Omron CX-Programmer project NuevoProyecto (CX-Programmer 9.50)

# PLC NewPLC1: CP1L-E EM

## Global symbols (name address type ; comment)
D0 CHANNEL  ; 0
T0002 BOOL  ; T2
T0003 BOOL  ; T3
T0004 BOOL  ; T4
T0005 BOOL  ; T5
T0006 BOOL  ; T6
T0007 BOOL  ; T7
T0008 BOOL  ; T8

## Program P10_2 (cyclic task 0)
Local symbols
EV1 100.04 BOOL  ; EV1=X6·Pm'
EV2 100.05 BOOL  ; EV2=X13·Pm'
EVA 100.00 BOOL  ; EVA=(X1+X10)·Pm'
EVB 100.01 BOOL  ; EVB=(X2+X9)Pm'
EVC 100.02 BOOL  ; EVC=X3·Pm'
EVD 100.03 BOOL  ; EVD=X8·Pm'
Etapa_0 10.00 BOOL
Etapa_1 10.01 BOOL
Etapa_10 10.10 BOOL
Etapa_11 10.11 BOOL
Etapa_12 10.12 BOOL
Etapa_13 10.13 BOOL
Etapa_14 10.14 BOOL
Etapa_2 10.02 BOOL
Etapa_3 10.03 BOOL
Etapa_4 10.04 BOOL
Etapa_5 10.05 BOOL
Etapa_6 10.06 BOOL
Etapa_7 10.07 BOOL
Etapa_8 10.08 BOOL
Etapa_9 10.09 BOOL
FC1 0.04 BOOL  ; Final carrera 1 (CNA)
FC2 0.05 BOOL  ; Final carrera 2 (CNA)
FC3 0.06 BOOL  ; Final carrera 3 (CNA)
FC4 0.07 BOOL  ; Final carrera 4 (CNA)
KCD 100.06 BOOL  ; KCD=(X1+X2+X3+X4)·Pm'
KCI 100.07 BOOL  ; KCI=(X8+X9+X10+X11)·Pm'
KV1D 101.00 BOOL  ; KV1D=X5·Pm'
KV1I 101.01 BOOL  ; KV1I=X7·Pm'
KV2D 101.02 BOOL  ; KV2D=X14·Pm'
KV2I 101.03 BOOL  ; KV2I=X12·Pm'
P 0.02 BOOL  ; Pulsador de paro (CNC)
Pm 15.00 BOOL  ; Pm=P·X0'+Pm·R'
R 0.03 BOOL  ; Pulsador de rearme (CNA)
m1 0.00 BOOL  ; Pulsador de marcha mezcla 1 (CNA)
m2 0.01 BOOL  ; Pulsador de marcha mezcla 2 (CNA)

### Section Sección1_Etapa_0

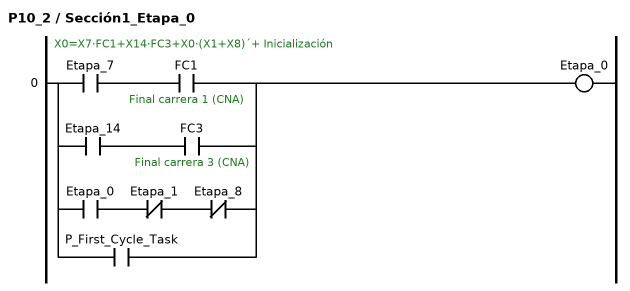
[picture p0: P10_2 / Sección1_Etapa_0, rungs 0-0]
; rung 0: X0=X7·FC1+X14·FC3+X0·(X1+X8)´+ Inicialización
LD Etapa_7
AND FC1  ; Final carrera 1 (CNA)
LD Etapa_14
AND FC3  ; Final carrera 3 (CNA)
ORLD
LD Etapa_0
ANDNOT Etapa_1
ANDNOT Etapa_8
ORLD
OR P_First_Cycle_Task
OUT Etapa_0

### Section Sección2_Mezcla_1_Etapas_1_a_7

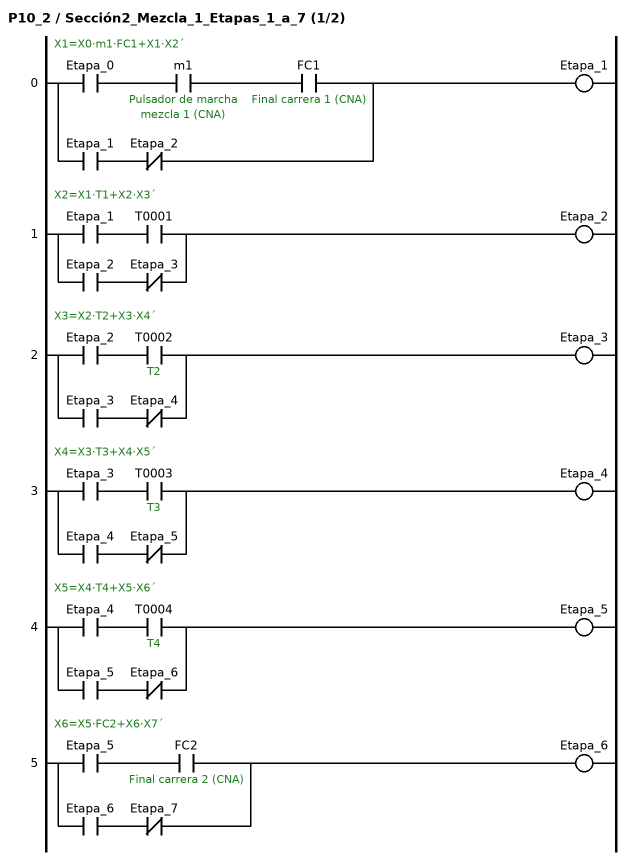
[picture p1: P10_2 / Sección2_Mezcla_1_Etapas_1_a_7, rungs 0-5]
; rung 0: X1=X0·m1·FC1+X1·X2´
LD Etapa_0
AND m1  ; Pulsador de marcha mezcla 1 (CNA)
AND FC1  ; Final carrera 1 (CNA)
LD Etapa_1
ANDNOT Etapa_2
ORLD
OUT Etapa_1
; rung 1: X2=X1·T1+X2·X3´
LD Etapa_1
AND T0001
LD Etapa_2
ANDNOT Etapa_3
ORLD
OUT Etapa_2
; rung 2: X3=X2·T2+X3·X4´
LD Etapa_2
AND T0002  ; T2
LD Etapa_3
ANDNOT Etapa_4
ORLD
OUT Etapa_3
; rung 3: X4=X3·T3+X4·X5´
LD Etapa_3
AND T0003  ; T3
LD Etapa_4
ANDNOT Etapa_5
ORLD
OUT Etapa_4
; rung 4: X5=X4·T4+X5·X6´
LD Etapa_4
AND T0004  ; T4
LD Etapa_5
ANDNOT Etapa_6
ORLD
OUT Etapa_5
; rung 5: X6=X5·FC2+X6·X7´
LD Etapa_5
AND FC2  ; Final carrera 2 (CNA)
LD Etapa_6
ANDNOT Etapa_7
ORLD
OUT Etapa_6

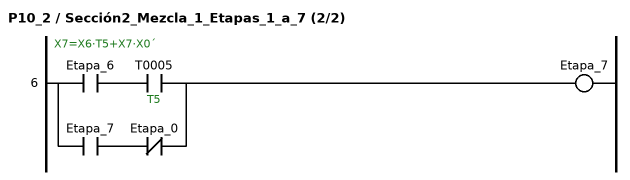
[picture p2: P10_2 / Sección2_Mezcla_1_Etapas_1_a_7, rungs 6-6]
; rung 6: X7=X6·T5+X7·X0´
LD Etapa_6
AND T0005  ; T5
LD Etapa_7
ANDNOT Etapa_0
ORLD
OUT Etapa_7

### Section Sección3_Mezcla_2_Etapas_8_a_14

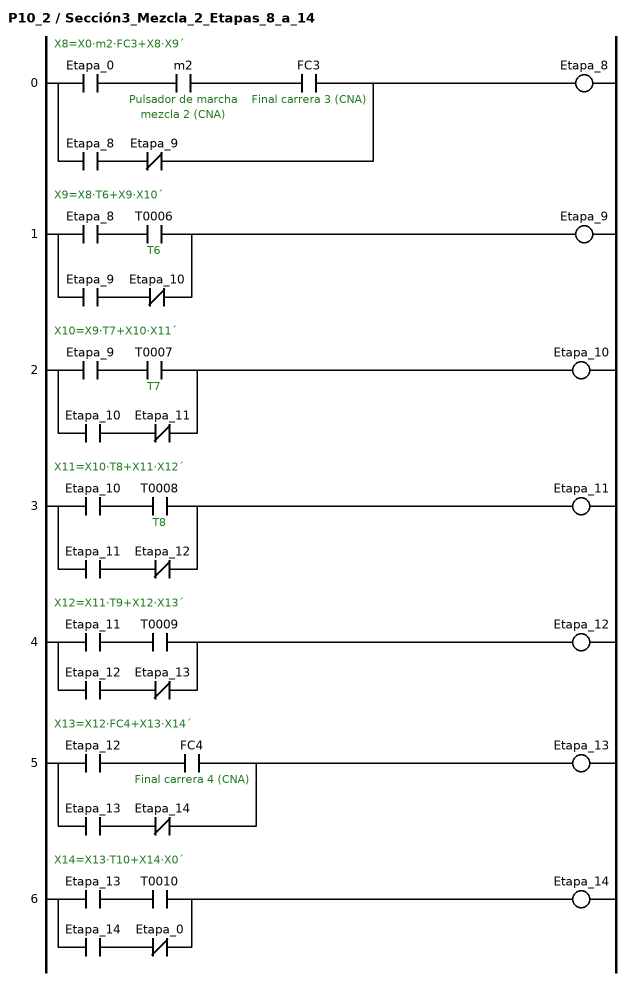
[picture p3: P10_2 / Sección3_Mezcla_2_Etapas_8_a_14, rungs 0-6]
; rung 0: X8=X0·m2·FC3+X8·X9´
LD Etapa_0
AND m2  ; Pulsador de marcha mezcla 2 (CNA)
AND FC3  ; Final carrera 3 (CNA)
LD Etapa_8
ANDNOT Etapa_9
ORLD
OUT Etapa_8
; rung 1: X9=X8·T6+X9·X10´
LD Etapa_8
AND T0006  ; T6
LD Etapa_9
ANDNOT Etapa_10
ORLD
OUT Etapa_9
; rung 2: X10=X9·T7+X10·X11´
LD Etapa_9
AND T0007  ; T7
LD Etapa_10
ANDNOT Etapa_11
ORLD
OUT Etapa_10
; rung 3: X11=X10·T8+X11·X12´
LD Etapa_10
AND T0008  ; T8
LD Etapa_11
ANDNOT Etapa_12
ORLD
OUT Etapa_11
; rung 4: X12=X11·T9+X12·X13´
LD Etapa_11
AND T0009
LD Etapa_12
ANDNOT Etapa_13
ORLD
OUT Etapa_12
; rung 5: X13=X12·FC4+X13·X14´
LD Etapa_12
AND FC4  ; Final carrera 4 (CNA)
LD Etapa_13
ANDNOT Etapa_14
ORLD
OUT Etapa_13
; rung 6: X14=X13·T10+X14·X0´
LD Etapa_13
AND T0010
LD Etapa_14
ANDNOT Etapa_0
ORLD
OUT Etapa_14

### Section Sección4_Temporizadores
; Temporizadores

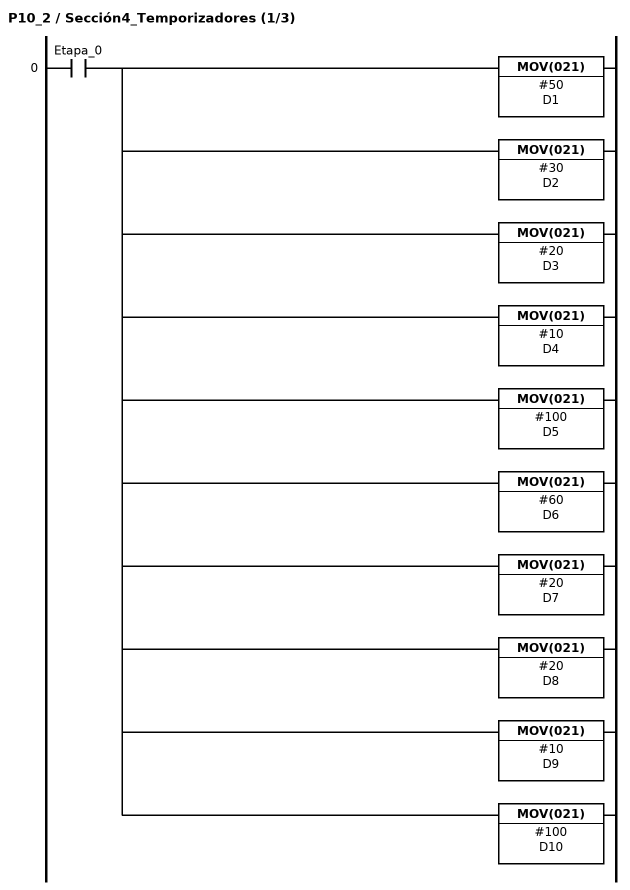
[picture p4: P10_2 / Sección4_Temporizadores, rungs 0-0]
; rung 0
LD Etapa_0
MOV(021) #50 D1
MOV(021) #30 D2
MOV(021) #20 D3
MOV(021) #10 D4
MOV(021) #100 D5
MOV(021) #60 D6
MOV(021) #20 D7
MOV(021) #20 D8
MOV(021) #10 D9
MOV(021) #100 D10

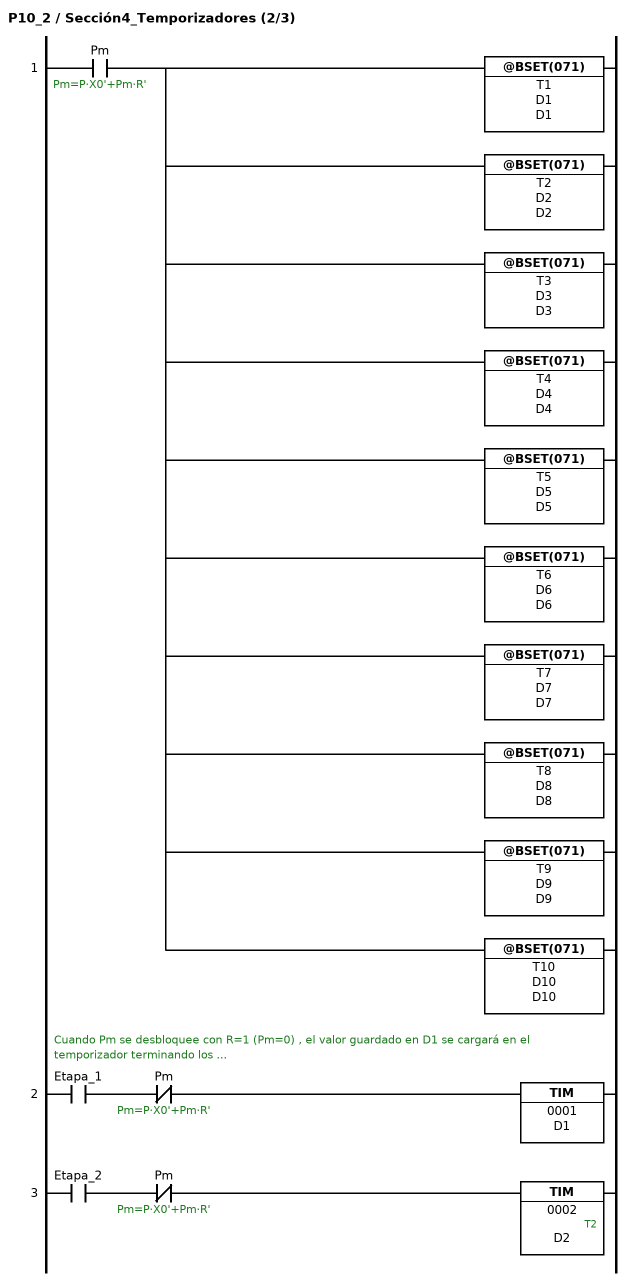
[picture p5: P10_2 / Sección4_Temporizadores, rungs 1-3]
; rung 1
LD Pm  ; Pm=P·X0'+Pm·R'
@BSET(071) T1 D1 D1  // La instrucción @BSET pasa a D1 el valor que le queda a T1 en el momento de pulsar P (Pm=1)
@BSET(071) T2 D2 D2
@BSET(071) T3 D3 D3
@BSET(071) T4 D4 D4
@BSET(071) T5 D5 D5
@BSET(071) T6 D6 D6
@BSET(071) T7 D7 D7
@BSET(071) T8 D8 D8
@BSET(071) T9 D9 D9
@BSET(071) T10 D10 D10
; rung 2: Cuando Pm se desbloquee con R=1 (Pm=0) , el valor guardado en D1 se cargará en el temporizador terminando los ...
LD Etapa_1
ANDNOT Pm  ; Pm=P·X0'+Pm·R'
TIM 0001 D1  // ... segundos que le quedasen
; rung 3
LD Etapa_2
ANDNOT Pm  ; Pm=P·X0'+Pm·R'
TIM 0002 D2  ; T2

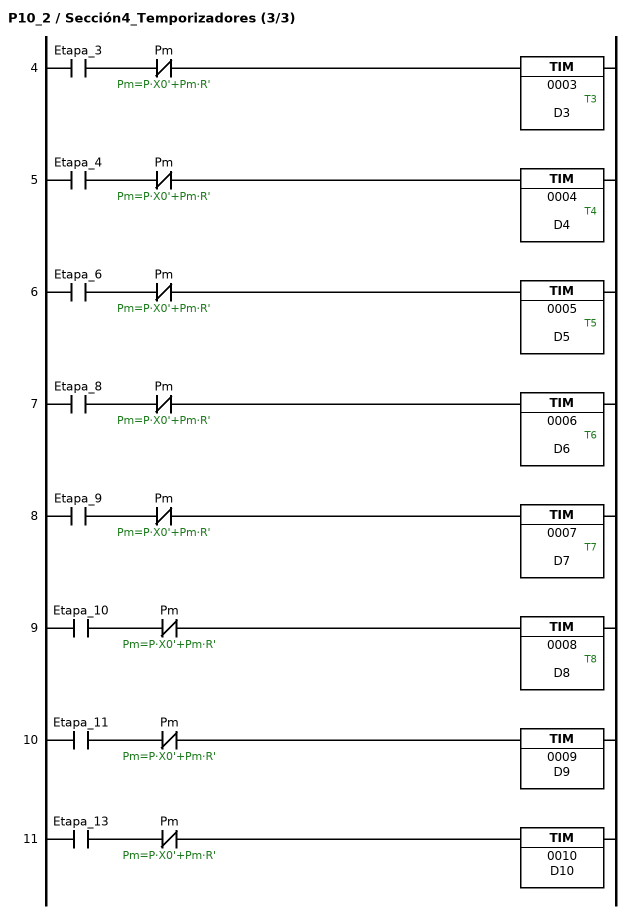
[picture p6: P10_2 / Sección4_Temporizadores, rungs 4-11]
; rung 4
LD Etapa_3
ANDNOT Pm  ; Pm=P·X0'+Pm·R'
TIM 0003 D3  ; T3
; rung 5
LD Etapa_4
ANDNOT Pm  ; Pm=P·X0'+Pm·R'
TIM 0004 D4  ; T4
; rung 6
LD Etapa_6
ANDNOT Pm  ; Pm=P·X0'+Pm·R'
TIM 0005 D5  ; T5
; rung 7
LD Etapa_8
ANDNOT Pm  ; Pm=P·X0'+Pm·R'
TIM 0006 D6  ; T6
; rung 8
LD Etapa_9
ANDNOT Pm  ; Pm=P·X0'+Pm·R'
TIM 0007 D7  ; T7
; rung 9
LD Etapa_10
ANDNOT Pm  ; Pm=P·X0'+Pm·R'
TIM 0008 D8  ; T8
; rung 10
LD Etapa_11
ANDNOT Pm  ; Pm=P·X0'+Pm·R'
TIM 0009 D9
; rung 11
LD Etapa_13
ANDNOT Pm  ; Pm=P·X0'+Pm·R'
TIM 0010 D10

### Section Sección5_Ecuación_Pm

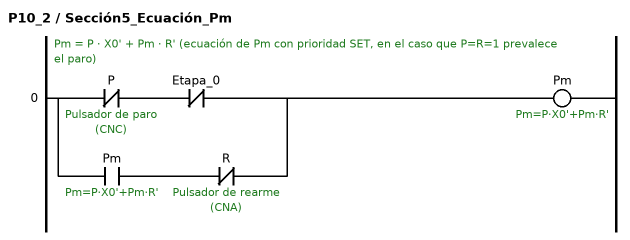
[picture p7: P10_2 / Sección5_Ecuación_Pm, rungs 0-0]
; rung 0: Pm = P · X0' + Pm · R' (ecuación de Pm con prioridad SET, en el caso que P=R=1 prevalece el paro)
LDNOT P  ; Pulsador de paro (CNC)
ANDNOT Etapa_0
LD Pm  ; Pm=P·X0'+Pm·R'
ANDNOT R  ; Pulsador de rearme (CNA)
ORLD
OUT Pm  ; Pm=P·X0'+Pm·R'

### Section Sección6_Salidas
; Salidas

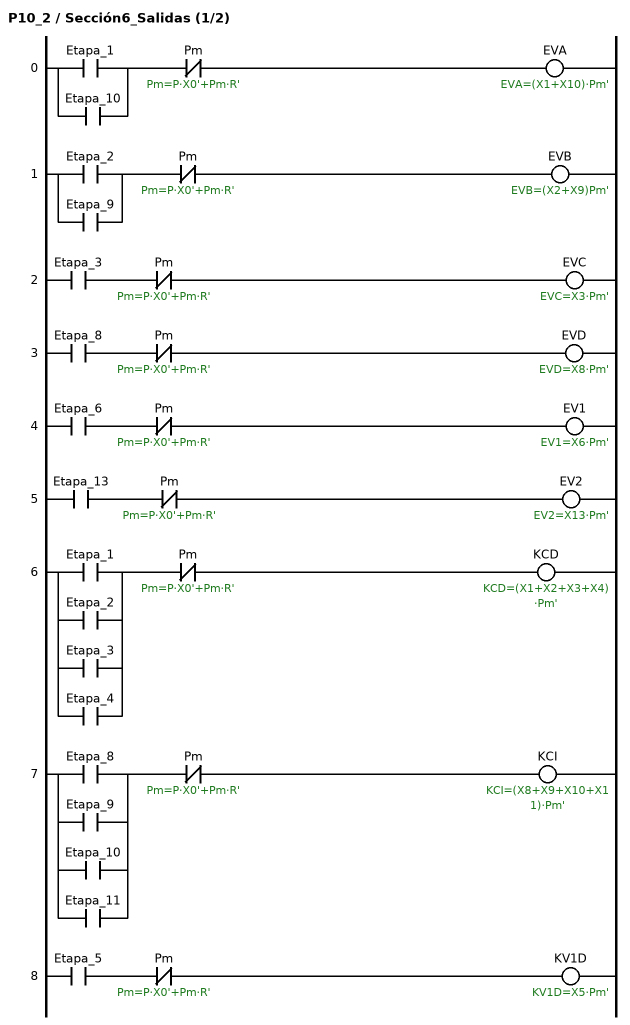
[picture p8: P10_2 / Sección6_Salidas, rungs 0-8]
; rung 0
LD Etapa_1
OR Etapa_10
ANDNOT Pm  ; Pm=P·X0'+Pm·R'
OUT EVA  ; EVA=(X1+X10)·Pm'
; rung 1
LD Etapa_2
OR Etapa_9
ANDNOT Pm  ; Pm=P·X0'+Pm·R'
OUT EVB  ; EVB=(X2+X9)Pm'
; rung 2
LD Etapa_3
ANDNOT Pm  ; Pm=P·X0'+Pm·R'
OUT EVC  ; EVC=X3·Pm'
; rung 3
LD Etapa_8
ANDNOT Pm  ; Pm=P·X0'+Pm·R'
OUT EVD  ; EVD=X8·Pm'
; rung 4
LD Etapa_6
ANDNOT Pm  ; Pm=P·X0'+Pm·R'
OUT EV1  ; EV1=X6·Pm'
; rung 5
LD Etapa_13
ANDNOT Pm  ; Pm=P·X0'+Pm·R'
OUT EV2  ; EV2=X13·Pm'
; rung 6
LD Etapa_1
OR Etapa_2
OR Etapa_3
OR Etapa_4
ANDNOT Pm  ; Pm=P·X0'+Pm·R'
OUT KCD  ; KCD=(X1+X2+X3+X4)·Pm'
; rung 7
LD Etapa_8
OR Etapa_9
OR Etapa_10
OR Etapa_11
ANDNOT Pm  ; Pm=P·X0'+Pm·R'
OUT KCI  ; KCI=(X8+X9+X10+X11)·Pm'
; rung 8
LD Etapa_5
ANDNOT Pm  ; Pm=P·X0'+Pm·R'
OUT KV1D  ; KV1D=X5·Pm'

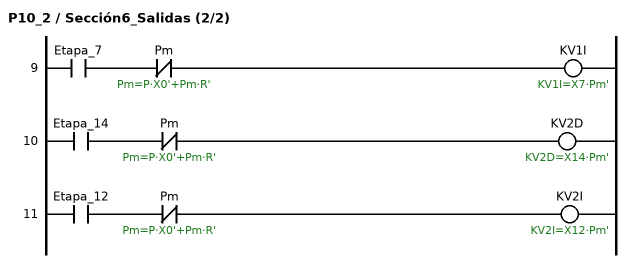
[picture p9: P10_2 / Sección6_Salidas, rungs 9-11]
; rung 9
LD Etapa_7
ANDNOT Pm  ; Pm=P·X0'+Pm·R'
OUT KV1I  ; KV1I=X7·Pm'
; rung 10
LD Etapa_14
ANDNOT Pm  ; Pm=P·X0'+Pm·R'
OUT KV2D  ; KV2D=X14·Pm'
; rung 11
LD Etapa_12
ANDNOT Pm  ; Pm=P·X0'+Pm·R'
OUT KV2I  ; KV2I=X12·Pm'

### Section Sección7_END
; END
; rung 0
END(001)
